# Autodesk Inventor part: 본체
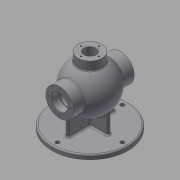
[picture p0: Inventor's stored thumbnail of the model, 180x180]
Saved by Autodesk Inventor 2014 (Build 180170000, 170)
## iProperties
Created: 2020-08
Part Number: 본체
Material: Generic
Document SubType Name: Modeling
Designer: kh
Density: 1 g/cm^3
Appearance: Default
Author: kh
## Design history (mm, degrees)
sketch "Sketch1"
  geometry: C1 r 85 at (0, 0); 1 further point
  constraints: 1 centre point, 1 coincident
  dimensions: "d0" = 170 diameter of C1
extrude "Extrusion1" new body sketch "Sketch1" distance "d1" = 10; taper "d2" = 0 deg
sketch "Sketch2"
  geometry: L1 (85, 10)-(-85, 10) reference; L2 (-85, 0)-(85, 0) reference; L3 (0, 0)-(0, 85); L4 (-68, 85)-(68, 85); L5 (-68, 102.5)-(-52, 102.5); L6 (-52, 102.5)-(-52, 103.5); L7 (-52, 103.5)-(-50.25, 103.5); L8 (-50.25, 103.5)-(-50.25, 102.5); L9 (-50.25, 102.5)-(-39.278, 102.5); L10 (39.278, 102.5)-(68, 102.5); L11 (68, 102.5)-(68, 116); L12 (68, 116)-(42.988, 116); L13 (-42.988, 116)-(-68, 116); L14 (-68, 116)-(-68, 102.5); L15 (68, 85)-(68, 0); A1 r 43 centre (0, 85) between (39.278, 102.5) and (-39.278, 102.5); A2 r 53 centre (0, 85) between (42.988, 116) and (-42.988, 116)
  constraints: 26 end point, 6 perpendicular, 4 collinear, 4 parallel, 4 point on circle, 2 centre point, 2 coincident, 2 point on line, 1 midpoint
  dimensions: "d3" = 85 distance of L3.end L3.start; "d4" = 136 distance of L4.start L4.end; "d5" = 43 radius of A1; "d6" = 16 distance of L5.start L5.end; "d7" = 35 diameter of L10 L4; "d9" = 136 distance between parallel lines of L11 L14; "d10" = 35 diameter of L5 L4; "d11" = 35 diameter of L9 L4; "d12" = 1.75 distance of L6.end L7.end; "d13" = 37 diameter of L7 L4; "d14" = 62 diameter of L12 L4; "d15" = 53 radius of A2
revolve "Revolution1" sketch "Sketch2" stored, may be unused: angle "d16" = 90 deg
sketch "Sketch3" dims "d17" = 48
  geometry: L1 (0, 0)-(0, -24); C1 r 31 at (0, 0) reference; C2 r 17.5 at (0, 0) reference; 1 further point
  constraints: 2 end point, 1 coincident, 1 vertical, 1 vertical alignment, 2 other
hole "Hole1" sketch "Sketch3" at (0, -24) diameter "d18" = 3.242; stored, may be unused: countersink angle "d22" = 90 deg, drill point angle "d24" = 118 deg; dims "d19" = 12, "d20" = 4, "d21" = 2, "d23" = 15
pattern_circular "Circular Pattern1" dims angle "d26" = 360 deg
mirror "Mirror1"
sketch "Sketch4" dims "d28" = 145
  geometry: L1 (0, 0)-(0, -72.5); C1 r 85 at (0, 0) reference; 2 further points
  constraints: 2 coincident, 2 end point, 1 vertical, 1 vertical alignment, 2 other
hole "Hole2" sketch "Sketch4" at (0, -72.5) diameter "d29" = 9; stored, may be unused: countersink angle "d33" = 90 deg, drill point angle "d35" = 0 deg; dims "d30" = 12, "d31" = 4, "d32" = 2, "d34" = 15
pattern_circular "Circular Pattern2" dims angle "d37" = 360 deg
sketch "Sketch6"
  geometry: L1 (85, 10)-(-85, 10) reference; L2 (-85, 0)-(85, 0) reference; L3 (0, 10)-(0, 32); L4 (0, 10)-(52, 10); L5 (42.988, 54)-(68, 54) reference; L6 (52, 10)-(52, 54); A1 r 53 centre (0, 85) between (42.988, 116) and (42.988, 54) reference; 1 further point
  constraints: 6 end point, 2 perpendicular, 2 point on line, 1 midpoint, 1 point on circle
  dimensions: "d40" = 52 distance of L3.start L4.end
feature "Rib1" sketch "Sketch6" dims "d41" = 1, "d42" = 8, "d43" = 0, "d44" = 0, "d45" = 1, "d46" = 1
mirror "Mirror2"
sketch "Sketch7"
  geometry: L1 (85, 10)-(-85, 10) reference; L2 (-85, 0)-(85, 0) reference; L3 (0, 0)-(0, 32.151); L4 (0, 0)-(43, 0); L5 (43, 0)-(43, 54.016); A1 r 53 centre (0, 85) between (4, 32.151) and (-4, 32.151) reference
  constraints: 6 end point, 2 perpendicular, 1 point on circle, 1 point on line
  dimensions: "d47" = 43 distance of L3.start L4.end
feature "Rib2" sketch "Sketch7" dims "d48" = 1, "d49" = 8, "d50" = 0, "d51" = 0, "d52" = 1, "d53" = 1
mirror "Mirror3"
workplane "Work Plane1"
sketch "Sketch8"
  geometry: C1 r 27 at (0, 0); 1 further point
  constraints: 1 centre point, 1 coincident
  dimensions: "d55" = 54 diameter of C1
extrude "Extrusion2" join sketch "Sketch8" stored distance "d56" = 10; taper "d57" = 0 deg
sketch "Sketch9"
  geometry: C1 r 13 at (0, 0); 1 further point
  constraints: 1 centre point, 1 coincident
  dimensions: "d58" = 26 diameter of C1
extrude "Extrusion3" cut sketch "Sketch9" stored distance "d59" = 10; taper "d60" = 0 deg
sketch "Sketch10" dims "d61" = 40
  geometry: L1 (0, 0)-(0, 20); 1 further point
  constraints: 2 end point, 1 coincident, 1 vertical, 1 vertical alignment, 2 other
hole "Hole3" sketch "Sketch10" at (0, 20) diameter "d62" = 3.242; stored, may be unused: countersink angle "d66" = 90 deg, drill point angle "d68" = 118 deg; dims "d63" = 12, "d64" = 4, "d65" = 2, "d67" = 15
pattern_circular "Circular Pattern3" dims angle "d70" = 360 deg
chamfer "Chamfer1" distance "d72" = 1; stored, may be unused: second distance "d73" = 2, angle "d74" = 45 deg
chamfer "Chamfer2" distance "d75" = 1; stored, may be unused: second distance "d76" = 2, angle "d77" = 45 deg
chamfer "Chamfer3" distance "d78" = 1; stored, may be unused: second distance "d79" = 2, angle "d80" = 45 deg
fillet "Fillet1" dims "d81" = 3
fillet "Fillet2" dims "d82" = 3
fillet "Fillet3" dims "d83" = 3
fillet "Fillet4" dims "d84" = 3
fillet "Fillet5" dims "d85" = 3
workplane "Work Plane2"
body "Solid1"
node "Projected Loop1"
node "Projected Loop2"
node "Projected Loop3"
node "Projected Loop4"
node "Projected Loop5"
